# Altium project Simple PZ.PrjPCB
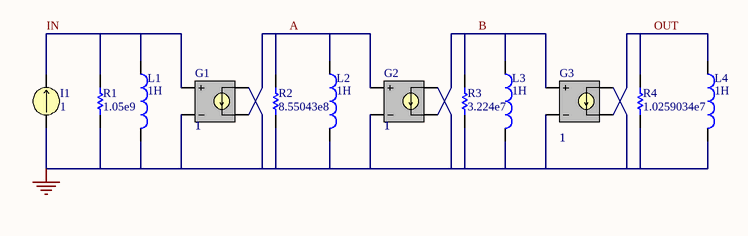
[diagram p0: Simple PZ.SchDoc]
1 sheet, 12 parts. Net scope: global (net labels, ports and power ports of the same name join across sheets).

## Sheet Simple PZ.SchDoc
size A4; Organization: Altium Limited; Address1: L3, 12a Rodborough Rd; Address2: Frenchs Forest; Address3: NSW; Address4: Australia 2086; DocumentNumber: 1; SheetNumber: 1; SheetTotal: 1

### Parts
G1  Gain: 1  (hidden comment: GSRC)
G2  Gain: 1  (hidden comment: GSRC)
G3  Gain: 1  (hidden comment: GSRC)
I1  1
L1  value 1H  [C1005-0402]  (hidden comment: Inductor)
L2  1H  [C1005-0402]
L3  1H  [C1005-0402]
L4  1H  [C1005-0402]
R1  1.05e9  [AXIAL-0.3]
R2  8.55043e8  [AXIAL-0.3]
R3  3.224e7  [AXIAL-0.3]
R4  1.0259034e7  [AXIAL-0.3]

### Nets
GND: G1.2(NC-) G1.3(N+) G2.2(NC-) G2.3(N+) G3.2(NC-) G3.3(N+) I1.1 L1.2 L2.2 L3.2 L4.2 R1.2 R2.2 R3.2 R4.2
A: G1.4(N-) G2.1(NC+) L2.1 R2.1
B: G2.4(N-) G3.1(NC+) L3.1 R3.1
IN: G1.1(NC+) I1.2 L1.1 R1.1
OUT: G3.4(N-) L4.1 R4.1

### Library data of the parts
G1-G3 = GSRC: Voltage Controlled Current Source; Manufacturer: Generic Components; Class I: Simulation; Note: PCB Footprint - Not required
I1 = ISRC: Current Source; Manufacturer: Generic Components; Class I: Simulation; Note: PCB Footprint - Not required
L1-L4 = Inductor: Manufacturer: Generic Components; Class I: Passive
R1-R4 = Res1: Resistor; Manufacturer: Generic Components; Class I: Passive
